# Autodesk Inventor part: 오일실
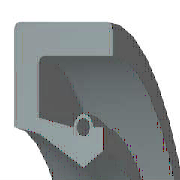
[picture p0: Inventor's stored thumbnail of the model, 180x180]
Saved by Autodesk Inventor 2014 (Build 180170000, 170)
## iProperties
IsCustomPart: 1
Created: 2015-12
Part Number: 오일실
Material: 고무
Description: 오일-실
Document SubType Name: Modeling
Standard: KS B 2804
Designer: mdu
Standards Organization: KS
Language: ko-KR
Size Designation: S - 15 30 7
Categories: <MemberInstance><Categories><Category DisplayName="샤프트 부품" InternalName="7f7aeb1f-a693-4053-b835-cee3144e0d98" Mnemonic="SHFT"><Category DisplayName="실링" Intern
Density: 0.93 g/cm^3
Mass: 1.64364 g
Surface Area: 26.6454 cm^2
Volume: 1.76736 cm^3
Appearance: 고무 - 검은색 - 버전 1.1
Author: mdu
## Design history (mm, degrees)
revolve "본체" stored, may be unused: angle "d17" = 90 deg
revolve "스프링1" stored, may be unused: angle "d18" = 90 deg
body "Solid1"
sketch "스케치1"
  geometry: L1 (0, 15)-(7, 15); L2 (7, 15)-(7, 13.75); L3 (7, 13.75)-(1.75, 13.75); L4 (0, 15)-(0, 9.6); L5 (0, 9.6)-(1.75, 9.25); L6 (1.75, 9.25)-(4.9, 7.5); L7 (4.9, 7.5)-(0, 7.5); L8 (6.3, 8.375)-(6.3, 9.6); L9 (0, 0)-(9.586, 0) reference; L10 (4.9, 7.5)-(6.3, 8.375); L11 (0, 18)-(0, -3) reference; L12 (-1.917, 0)-(11.503, 0) reference; L13 (4.2, 9.6)-(1.75, 10.09); L14 (1.75, 10.09)-(1.75, 13.75); L15 (6.3, 9.6)-(5.6, 9.6); C1 r 0.455 at (4.9, 9.6); A1 r 0.7 centre (4.9, 9.6) between (5.6, 9.6) and (4.2, 9.6)
  constraints: 26 end point, 5 horizontal alignment, 4 perpendicular, 2 centre point, 2 collinear, 2 horizontal, 2 parallel, 2 point on circle, 2 point on line, 2 vertical alignment, 1 coincident
  dimensions: "d0" = 30 diameter of L1 L9 (= SD2); "d1" = 16.75 diameter of L8.start L9 (= ABDM); "d2" = 1.25 distance of L1.end L2.end (computed from SD); "d3" = 0.91 diameter of C1 (= SPDI); "d4" = 1.4 diameter of A1 (= SPDA); "d5" = 15 diameter of L6.end L9 (= NND); "d6" = 18.5 diameter of L5.end L9 (= TKDM); "d7" = 19.2 diameter of L4.end L9 (= HLDM); "d8" = 4.9 distance from line of C1.centre L4 (= SPDST); "d9" = 6.3 distance between parallel lines of L8 L4 (= SDI); "d10" = 7 distance between parallel lines of L2 L4 (= SWDT); "d12" = 1.75 distance between parallel lines of L14 L4 (= SD)
fillet "모깎기1" dims "d11" = 0.3 (= RR)
other parameters: "SD2" = 30 [user parameter; used in 1 equation term], "SWDT" = 7 [user parameter; used in 1 equation term], "RR" = 0.3 [user parameter; used in 1 equation term], "SD" = 1.75 [user parameter; used in 2 equation terms], "NND" = 15 [user parameter; used in 1 equation term], "SPDA" = 1.4 [user parameter; used in 1 equation term], "SPDI" = 0.91 [user parameter; used in 1 equation term], "TKDM" = 18.5 [user parameter; used in 1 equation term], "HLDM" = 19.2 [user parameter; used in 1 equation term], "ABDM" = 16.75 [user parameter; used in 1 equation term], "SDI" = 6.3 [user parameter; used in 1 equation term], "SPDST" = 4.9 [user parameter; used in 1 equation term], "d13" = 0, "d14" = 0, "d15" = 0, "LAB" = 0.35 [user parameter]
